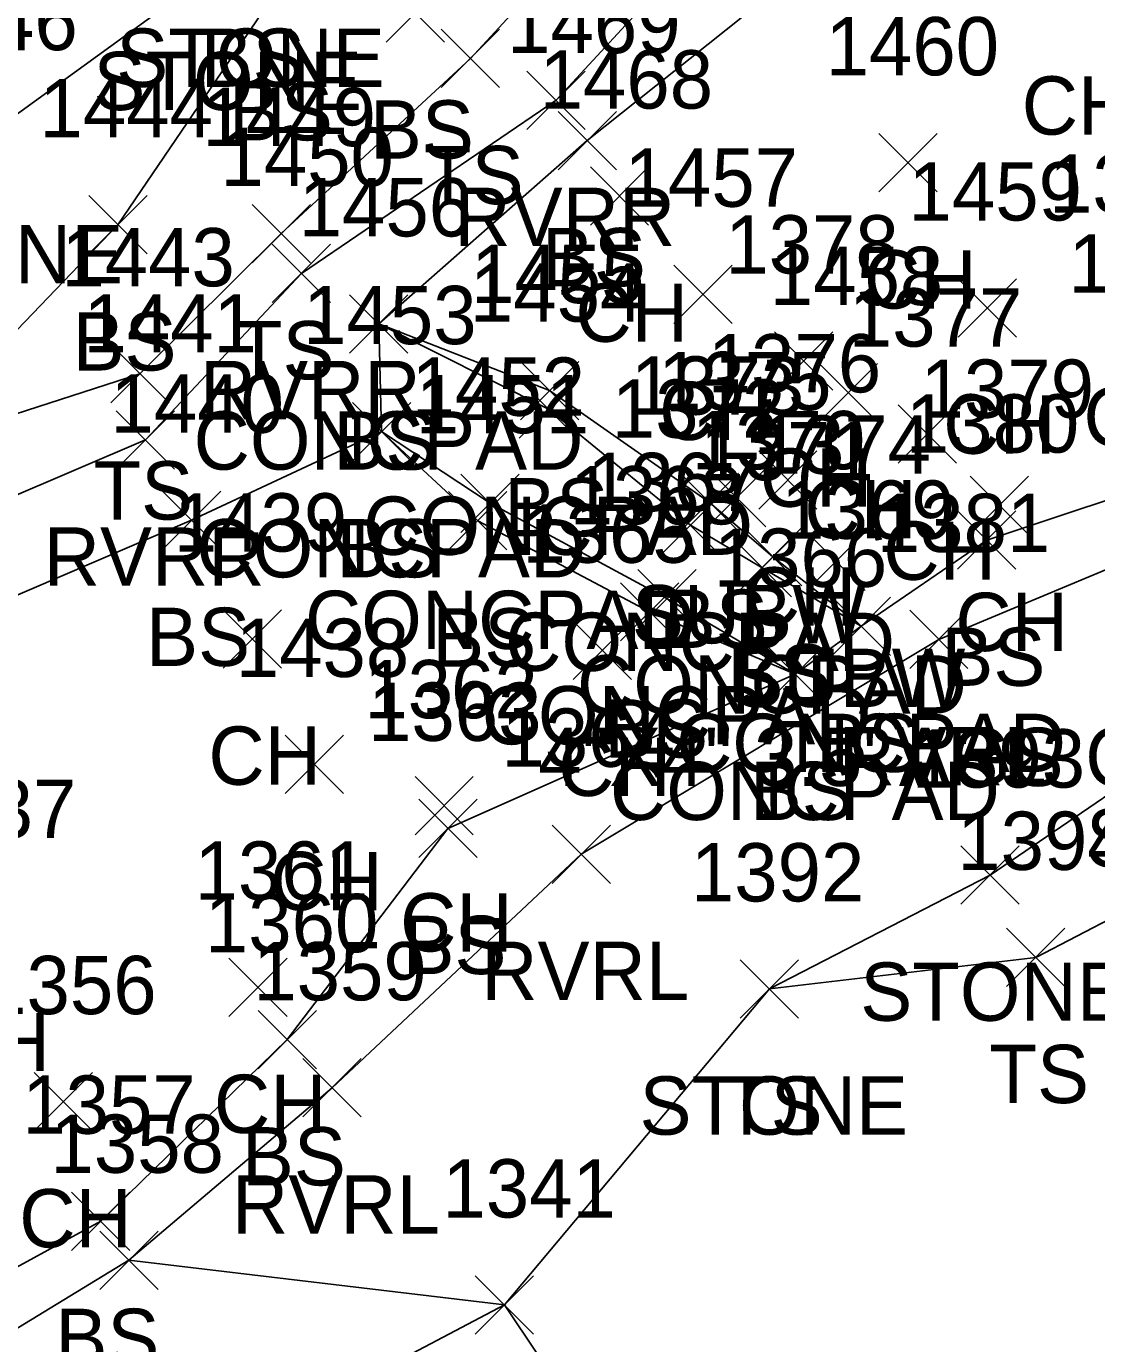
# Model space of a CAD drawing. Extents: x 1537342 to 1542195, y 163002 to 168596.
# Drawn here: x 1541735.99 to 1541772.7, y 163274.1 to 163319.29 of the extents above; entities that cross this region are included whole.
import ezdxf

# ---------------------------------------------------------------- set-up
doc = ezdxf.new("R2010")
doc.units = 0
for name, color, linetype in [('L_A', 7, 'Continuous'), ('L_I', 7, 'Continuous'), ('L_TIC', 7, 'Continuous'), ('LASF', 7, 'Continuous'), ('LAWA', 7, 'Continuous'), ('LAWE', 7, 'Continuous'), ('LELB', 7, 'Continuous'), ('LS', 7, 'Continuous'), ('M_C', 7, 'Continuous'), ('U_A', 7, 'Continuous'), ('U_I', 7, 'Continuous'), ('U_TIC', 7, 'Continuous')]:
    doc.layers.add(name, color=color, linetype=linetype)

msp = doc.modelspace()

# ---------------------------------------------------------------- linework, layer by layer
at = {"layer": 'L_TIC'}
for points in [[(1541748.33, 163318.749), (1541750.33, 163320.749)], [(1541750.33, 163318.749), (1541748.33, 163320.749)], [(1541750.219, 163317.185), (1541752.219, 163319.185)], [(1541752.219, 163317.185), (1541750.219, 163319.185)], [(1541753.159, 163315.751), (1541755.159, 163317.751)], [(1541755.159, 163315.751), (1541753.159, 163317.751)], [(1541754.23, 163314.369), (1541756.23, 163316.369)], [(1541756.23, 163314.369), (1541754.23, 163316.369)], [(1541765.234, 163313.606), (1541767.234, 163315.606)], [(1541767.234, 163313.606), (1541765.234, 163315.606)], [(1541755.336, 163312.465), (1541757.336, 163314.465)], [(1541757.336, 163312.465), (1541755.336, 163314.465)], [(1541738.13, 163311.48), (1541740.13, 163313.48)], [(1541740.13, 163311.48), (1541738.13, 163313.48)], [(1541743.733, 163311.178), (1541745.733, 163313.178)], [(1541745.733, 163311.178), (1541743.733, 163313.178)], [(1541744.426, 163309.811), (1541746.426, 163311.811)], [(1541746.426, 163309.811), (1541744.426, 163311.811)], [(1541758.204, 163309.097), (1541760.204, 163311.097)], [(1541760.204, 163309.097), (1541758.204, 163311.097)], [(1541767.951, 163308.626), (1541769.951, 163310.626)], [(1541769.951, 163308.626), (1541767.951, 163310.626)], [(1541747.078, 163308.08), (1541749.078, 163310.08)], [(1541749.078, 163308.08), (1541747.078, 163310.08)], [(1541747.078, 163308.08), (1541749.078, 163310.08)], [(1541749.078, 163308.08), (1541747.078, 163310.08)], [(1541747.078, 163308.08), (1541749.078, 163310.08)], [(1541749.078, 163308.08), (1541747.078, 163310.08)], [(1541761.658, 163306.807), (1541763.658, 163308.807)], [(1541763.658, 163306.807), (1541761.658, 163308.807)], [(1541738.882, 163306.368), (1541740.882, 163308.368)], [(1541740.882, 163306.368), (1541738.882, 163308.368)], [(1541752.936, 163305.794), (1541754.936, 163307.794)], [(1541754.936, 163305.794), (1541752.936, 163307.794)], [(1541763.184, 163305.726), (1541765.184, 163307.726)], [(1541765.184, 163305.726), (1541763.184, 163307.726)], [(1541752.896, 163305.158), (1541754.896, 163307.158)], [(1541754.896, 163305.158), (1541752.896, 163307.158)], [(1541739.071, 163304.099), (1541741.071, 163306.099)], [(1541741.071, 163304.099), (1541739.071, 163306.099)], [(1541747.176, 163304.385), (1541749.176, 163306.385)], [(1541749.176, 163304.385), (1541747.176, 163306.385)], [(1541747.176, 163304.385), (1541749.176, 163306.385)], [(1541749.176, 163304.385), (1541747.176, 163306.385)], [(1541747.176, 163304.385), (1541749.176, 163306.385)], [(1541749.176, 163304.385), (1541747.176, 163306.385)], [(1541765.897, 163304.301), (1541767.897, 163306.301)], [(1541767.897, 163304.301), (1541765.897, 163306.301)], [(1541761.11, 163302.73), (1541763.11, 163304.73)], [(1541763.11, 163302.73), (1541761.11, 163304.73)], [(1541750.896, 163301.928), (1541752.896, 163303.928)], [(1541752.896, 163301.928), (1541750.896, 163303.928)], [(1541758.413, 163301.965), (1541760.413, 163303.965)], [(1541760.413, 163301.965), (1541758.413, 163303.965)], [(1541768.366, 163301.858), (1541770.366, 163303.858)], [(1541770.366, 163301.858), (1541768.366, 163303.858)], [(1541740.654, 163301.345), (1541742.654, 163303.345)], [(1541742.654, 163301.345), (1541740.654, 163303.345)], [(1541750.471, 163301.327), (1541752.471, 163303.327)], [(1541752.471, 163301.327), (1541750.471, 163303.327)], [(1541757.767, 163301.175), (1541759.767, 163303.175)], [(1541759.767, 163301.175), (1541757.767, 163303.175)], [(1541767.936, 163300.664), (1541769.936, 163302.664)], [(1541769.936, 163300.664), (1541767.936, 163302.664)], [(1541760.596, 163300.093), (1541762.596, 163302.093)], [(1541762.596, 163300.093), (1541760.596, 163302.093)], [(1541760.234, 163299.715), (1541762.234, 163301.715)], [(1541762.234, 163299.715), (1541760.234, 163301.715)], [(1541756.962, 163298.657), (1541758.962, 163300.657)], [(1541758.962, 163298.657), (1541756.962, 163300.657)], [(1541756.367, 163298.203), (1541758.367, 163300.203)], [(1541758.367, 163298.203), (1541756.367, 163300.203)], [(1541763.631, 163297.709), (1541765.631, 163299.709)], [(1541765.631, 163297.709), (1541763.631, 163299.709)], [(1541763.631, 163297.709), (1541765.631, 163299.709)], [(1541765.631, 163297.709), (1541763.631, 163299.709)], [(1541763.631, 163297.709), (1541765.631, 163299.709)], [(1541765.631, 163297.709), (1541763.631, 163299.709)], [(1541742.745, 163297.27), (1541744.745, 163299.27)], [(1541744.745, 163297.27), (1541742.745, 163299.27)], [(1541754.742, 163296.885), (1541756.742, 163298.885)], [(1541756.742, 163296.885), (1541754.742, 163298.885)], [(1541766.29, 163297.255), (1541768.29, 163299.255)], [(1541768.29, 163297.255), (1541766.29, 163299.255)], [(1541761.364, 163296.061), (1541763.364, 163298.061)], [(1541763.364, 163296.061), (1541761.364, 163298.061)], [(1541761.364, 163296.061), (1541763.364, 163298.061)], [(1541763.364, 163296.061), (1541761.364, 163298.061)], [(1541761.364, 163296.061), (1541763.364, 163298.061)], [(1541763.364, 163296.061), (1541761.364, 163298.061)], [(1541744.863, 163292.969), (1541746.863, 163294.969)], [(1541746.863, 163292.969), (1541744.863, 163294.969)], [(1541749.321, 163291.551), (1541751.321, 163293.551)], [(1541751.321, 163291.551), (1541749.321, 163293.551)], [(1541749.449, 163290.776), (1541751.449, 163292.776)], [(1541751.449, 163290.776), (1541749.449, 163292.776)], [(1541754.026, 163289.887), (1541756.026, 163291.887)], [(1541756.026, 163289.887), (1541754.026, 163291.887)], [(1541768.05, 163289.174), (1541770.05, 163291.174)], [(1541770.05, 163289.174), (1541768.05, 163291.174)], [(1541769.616, 163286.35), (1541771.616, 163288.35)], [(1541771.616, 163286.35), (1541769.616, 163288.35)], [(1541742.933, 163285.326), (1541744.933, 163287.326)], [(1541744.933, 163285.326), (1541742.933, 163287.326)], [(1541760.478, 163285.268), (1541762.478, 163287.268)], [(1541762.478, 163285.268), (1541760.478, 163287.268)], [(1541760.478, 163285.268), (1541762.478, 163287.268)], [(1541762.478, 163285.268), (1541760.478, 163287.268)], [(1541743.939, 163283.528), (1541745.939, 163285.528)], [(1541745.939, 163283.528), (1541743.939, 163285.528)], [(1541745.473, 163281.876), (1541747.473, 163283.876)], [(1541747.473, 163281.876), (1541745.473, 163283.876)], [(1541736.254, 163281.402), (1541738.254, 163283.402)], [(1541738.254, 163281.402), (1541736.254, 163283.402)], [(1541737.542, 163277.299), (1541739.542, 163279.299)], [(1541739.542, 163277.299), (1541737.542, 163279.299)], [(1541738.509, 163275.959), (1541740.509, 163277.959)], [(1541740.509, 163275.959), (1541738.509, 163277.959)], [(1541738.509, 163275.959), (1541740.509, 163277.959)], [(1541740.509, 163275.959), (1541738.509, 163277.959)], [(1541751.386, 163274.426), (1541753.386, 163276.426)], [(1541753.386, 163274.426), (1541751.386, 163276.426)], [(1541751.386, 163274.426), (1541753.386, 163276.426)], [(1541753.386, 163274.426), (1541751.386, 163276.426)]]:
    msp.add_lwpolyline(points, dxfattribs=at)
at = {"layer": 'LASF'}
for points in [[(1541725.244, 163309.572), (1541734.551, 163315.469), (1541742.746, 163321.414), (1541743.526, 163322.211), (1541748.762, 163326.379), (1541753.474, 163327.4)], [(1541752.386, 163275.426), (1541761.478, 163286.268), (1541769.05, 163290.174), (1541776.791, 163295.449), (1541785.876, 163300.883), (1541787.179, 163300.797), (1541790.864, 163303.749)], [(1541739.509, 163276.959), (1541752.386, 163275.426)]]:
    msp.add_lwpolyline(points, dxfattribs=at)
at = {"layer": 'LAWA'}
msp.add_lwpolyline([(1541844.856, 163168.927), (1541849.554, 163183.808), (1541839.113, 163205.97), (1541817.649, 163223.226), (1541815.003, 163239.805), (1541816.556, 163255.639), (1541792.396, 163274.279), (1541779.243, 163270.522), (1541762.882, 163259.76), (1541752.386, 163275.426), (1541738.683, 163268.208), (1541722.173, 163262.13), (1541701.078, 163257.123)], dxfattribs=at)
at = {"layer": 'LAWE'}
for points in [[(1541677.778, 163293.444), (1541698.285, 163296.179), (1541716.759, 163297.211), (1541728.014, 163299.943), (1541740.071, 163305.099), (1541745.426, 163310.811), (1541754.159, 163316.751), (1541763.565, 163326.932)], [(1541697.567, 163262.542), (1541711.727, 163266.963), (1541730.099, 163271.239), (1541739.509, 163276.959), (1541746.473, 163282.876), (1541755.026, 163290.887), (1541767.29, 163298.255), (1541776.81, 163302.235), (1541780.896, 163305.154), (1541791.033, 163307.198)]]:
    msp.add_lwpolyline(points, dxfattribs=at)
at = {"layer": 'LELB'}
for points in [[(1541680.476, 163291.861), (1541699.97, 163293.9), (1541717.141, 163294.135), (1541730.523, 163297.571), (1541741.654, 163302.345), (1541748.176, 163305.385), (1541748.078, 163309.08), (1541755.23, 163315.369), (1541766.506, 163324.36), (1541774.317, 163324.466), (1541783.87, 163329.52), (1541794.382, 163332.118), (1541806.545, 163337.396), (1541818.819, 163343.081), (1541839.231, 163350.559), (1541851.311, 163354.645), (1541860.204, 163362.664), (1541879.488, 163366.965), (1541895.128, 163366.199), (1541914.254, 163372.826), (1541910.846, 163375.465), (1541893.701, 163387.218), (1541872.662, 163402.005), (1541849.049, 163411.834)], [(1541724.974, 163304.042), (1541731.669, 163304.713), (1541739.882, 163307.368), (1541744.733, 163312.178), (1541751.219, 163318.185), (1541759.413, 163327.06)], [(1541731.669, 163304.713), (1541739.13, 163312.48), (1541744.492, 163320.375), (1541749.33, 163319.749), (1541754.806, 163327.195)], [(1541697.383, 163265.202), (1541711.185, 163268.467), (1541728.727, 163272.935), (1541738.542, 163278.299), (1541744.939, 163284.528), (1541750.449, 163291.776), (1541762.364, 163297.061), (1541764.631, 163298.709), (1541768.936, 163301.664), (1541775.915, 163303.982), (1541780.379, 163306.769), (1541791.076, 163308.949)], [(1541764.631, 163298.709), (1541761.596, 163301.093), (1541759.413, 163302.965), (1541753.936, 163306.794), (1541748.078, 163309.08)], [(1541762.364, 163297.061), (1541757.367, 163299.203), (1541751.471, 163302.327), (1541748.176, 163305.385)], [(1541761.478, 163286.268), (1541770.616, 163287.35), (1541779.056, 163291.741), (1541786.245, 163296.885)]]:
    msp.add_lwpolyline(points, dxfattribs=at)
at = {"layer": 'LS'}
for points in [[(1541764.631, 163298.709), (1541761.234, 163300.715), (1541758.767, 163302.175), (1541753.896, 163306.158), (1541748.078, 163309.08)], [(1541762.364, 163297.061), (1541757.962, 163299.657), (1541751.896, 163302.928), (1541748.176, 163305.385)]]:
    msp.add_lwpolyline(points, dxfattribs=at)
at = {"layer": 'U_TIC'}
for points in [[(1541759.35, 163302.121), (1541761.35, 163304.121)], [(1541761.35, 163302.121), (1541759.35, 163304.121)], [(1541762.767, 163299.938), (1541764.767, 163301.938)], [(1541764.767, 163299.938), (1541762.767, 163301.938)]]:
    msp.add_lwpolyline(points, dxfattribs=at)

# ---------------------------------------------------------------- texts
at = {"layer": 'L_A'}
for s, p in [('STONE', (1541739.07, 163317.211)), ('BS', (1541741.967, 163317.211)), ('STONE', (1541738.289, 163316.414)), ('BS', (1541742.933, 163315.375)), ('CH', (1541770.134, 163315.572)), ('BS', (1541747.771, 163314.749)), ('TS', (1541749.629, 163313.185)), ('RVRR', (1541750.671, 163311.751)), ('STONE', (1541730.094, 163310.469)), ('BS', (1541753.671, 163310.369)), ('CH', (1541764.722, 163309.606)), ('CH', (1541754.824, 163308.465)), ('BS', (1541737.571, 163307.48)), ('TS', (1541743.142, 163307.178)), ('RVRR', (1541741.938, 163305.811)), ('CH', (1541757.693, 163305.097)), ('CH', (1541767.439, 163304.626)), ('CH', (1541772.251, 163304.895)), ('CONCPAD', (1541741.724, 163304.08)), ('BS', (1541746.519, 163304.08)), ('BS', (1541746.519, 163304.08)), ('CH', (1541761.146, 163302.807)), ('TS', (1541738.291, 163302.368)), ('BS', (1541752.377, 163301.794)), ('CH', (1541762.672, 163301.726)), ('CONCPAD', (1541747.541, 163301.158)), ('RVRR', (1541736.583, 163300.099)), ('CONCPAD', (1541741.821, 163300.385)), ('BS', (1541746.617, 163300.385)), ('BS', (1541746.617, 163300.385)), ('CH', (1541765.385, 163300.301)), ('CH', (1541760.598, 163298.73)), ('CONCPAD', (1541745.542, 163297.928)), ('BS', (1541757.854, 163297.965)), ('CH', (1541767.854, 163297.858)), ('BS', (1541740.095, 163297.345)), ('BS', (1541749.912, 163297.327)), ('CONCPAD', (1541752.413, 163297.175)), ('BS', (1541767.377, 163296.664)), ('BS', (1541760.037, 163296.093)), ('CONCPAD', (1541754.879, 163295.715)), ('CONCPAD', (1541751.607, 163294.657)), ('BS', (1541755.808, 163294.203)), ('CONCPAD', (1541758.277, 163293.709)), ('BS', (1541763.072, 163293.709)), ('BS', (1541763.072, 163293.709)), ('CH', (1541742.233, 163293.27)), ('RVRL', (1541763.857, 163293.255)), ('CH', (1541754.231, 163292.885)), ('CONCPAD', (1541756.009, 163292.061)), ('BS', (1541760.805, 163292.061)), ('BS', (1541760.805, 163292.061)), ('STONE', (1541772.334, 163290.449)), ('CH', (1541744.351, 163288.969)), ('CH', (1541748.809, 163287.551)), ('BS', (1541748.89, 163286.776)), ('RVRL', (1541751.593, 163285.887)), ('STONE', (1541764.594, 163285.174)), ('CH', (1541732.934, 163283.447)), ('TS', (1541769.025, 163282.35)), ('CH', (1541742.421, 163281.326)), ('STONE', (1541757.022, 163281.268)), ('TS', (1541759.888, 163281.268)), ('BS', (1541743.38, 163279.528)), ('RVRL', (1541743.04, 163277.876)), ('CH', (1541735.742, 163277.402)), ('BS', (1541736.983, 163273.299))]:
    msp.add_text(s, height=2, dxfattribs=at).set_placement(p)
at = {"layer": 'L_I'}
for s, p in [('1446', (1541731.803, 163318.469)), ('1469', (1541752.482, 163318.369)), ('1460', (1541763.407, 163317.606)), ('1468', (1541753.596, 163316.465)), ('1444', (1541736.437, 163315.48)), ('1449', (1541742.032, 163315.178)), ('1450', (1541742.646, 163313.811)), ('1457', (1541756.512, 163313.097)), ('1459', (1541766.251, 163312.626)), ('1385', (1541771.07, 163312.895)), ('1456', (1541745.33, 163312.08)), ('1456', (1541745.33, 163312.08)), ('1456', (1541745.33, 163312.08)), ('1378', (1541759.966, 163310.807)), ('1443', (1541737.189, 163310.368)), ('1384', (1541771.734, 163310.153)), ('1455', (1541751.243, 163309.794)), ('1458', (1541761.492, 163309.726)), ('1454', (1541751.203, 163309.158)), ('1453', (1541745.483, 163308.385)), ('1453', (1541745.483, 163308.385)), ('1453', (1541745.483, 163308.385)), ('1377', (1541764.204, 163308.301)), ('1441', (1541737.945, 163308.099)), ('1376', (1541759.362, 163306.73)), ('1452', (1541749.204, 163305.928)), ('1373', (1541756.721, 163305.965)), ('1379', (1541766.665, 163305.858)), ('1440', (1541738.874, 163305.345)), ('1451', (1541749.345, 163305.327)), ('1372', (1541756.074, 163305.175)), ('1380', (1541766.157, 163304.664)), ('1370', (1541758.817, 163304.093)), ('1371', (1541759.108, 163303.715)), ('1367', (1541755.222, 163302.657)), ('1368', (1541754.627, 163302.203)), ('1369', (1541761.883, 163301.709)), ('1369', (1541761.883, 163301.709)), ('1369', (1541761.883, 163301.709)), ('1439', (1541741.045, 163301.27)), ('1365', (1541753.003, 163300.885)), ('1381', (1541765.164, 163301.255)), ('1366', (1541759.569, 163300.061)), ('1366', (1541759.569, 163300.061)), ('1366', (1541759.569, 163300.061)), ('1438', (1541743.171, 163296.969)), ('1362', (1541747.581, 163295.551)), ('1363', (1541747.709, 163294.776)), ('1364', (1541752.286, 163293.887)), ('1393', (1541766.358, 163293.174)), ('1437', (1541731.753, 163291.447)), ('1394', (1541767.923, 163290.35)), ('1361', (1541741.76, 163289.326)), ('1392', (1541758.785, 163289.268)), ('1392', (1541758.785, 163289.268)), ('1360', (1541742.113, 163287.528)), ('1359', (1541743.773, 163285.876)), ('1356', (1541734.506, 163285.402)), ('1357', (1541735.849, 163281.299)), ('1358', (1541736.816, 163279.959)), ('1358', (1541736.816, 163279.959)), ('1341', (1541750.261, 163278.426)), ('1341', (1541750.261, 163278.426))]:
    msp.add_text(s, height=2, dxfattribs=at).set_placement(p)
at = {"layer": 'M_C'}
msp.add_text('4"X4" 3.5\' AGS CONCRETE LEANING', height=2, dxfattribs=at).set_placement((1541753.548, 163293.228))
at = {"layer": 'U_A'}
for p in [(1541756.759, 163298.121), (1541760.176, 163295.938)]:
    msp.add_text('SUBW', height=2, dxfattribs=at).set_placement(p)
at = {"layer": 'U_I'}
for s, p in [('1375', (1541757.657, 163306.121)), ('1374', (1541761.074, 163303.938))]:
    msp.add_text(s, height=2, dxfattribs=at).set_placement(p)

doc.saveas('drawing.dxf')
